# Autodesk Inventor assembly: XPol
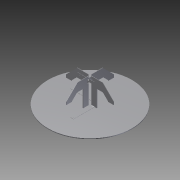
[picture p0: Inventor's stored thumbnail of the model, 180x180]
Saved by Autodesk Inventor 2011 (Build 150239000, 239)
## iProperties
Created: 2014-11
Part Number: XPol
Document SubType Name: Assembly
Designer: Evgeny
Author: Evgeny
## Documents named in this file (5)
- D:\Autodesk Invertor 2011\Projects2014\Antenna\Xpol\XPol.iam
- D:\Autodesk Invertor 2011\Projects2014\Antenna\Xpol\XPref.ipt
- D:\Autodesk Invertor 2011\Projects2014\Antenna\Xpol\Xp1.ipt
- D:\Autodesk Invertor 2011\Projects2014\Antenna\Xpol\XPstripeL.ipt
- D:\Autodesk Invertor 2011\Projects2014\Antenna\Xpol\XPstripe.ipt
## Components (7 placed, 4 different names)
1. XPref:1 — Совмещение:1, Совмещение:2, Совмещение:3, Совмещение:4, Совмещение:5, Совмещение:6, Совмещение:7, Совмещение:8, Совмещение:9, Совмещение:10, Совмещение:11, Совмещение:12, Совмещение:14, Совмещение:16
2. Xp1:1 — Совмещение:1, Совмещение:2, Совмещение:3, Совмещение:13
3. Xp1:2 — Совмещение:4, Совмещение:5, Совмещение:6, Совмещение:15
4. Xp1:3 — Совмещение:7, Совмещение:8, Совмещение:9, Заподлицо:2
5. Xp1:4 — Совмещение:10, Совмещение:11, Совмещение:12, Заподлицо:1
6. XPstripeL:1 — Совмещение:13, Совмещение:14, Заподлицо:1
7. XPstripe:1 — Совмещение:15, Совмещение:16, Заподлицо:2
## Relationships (18: Mate 16, Flush 2)
- Совмещение:1 [Mate]: XPref:1 ↔ Xp1:1
- Совмещение:2 [Mate]: XPref:1 ↔ Xp1:1
- Совмещение:3 [Mate]: XPref:1 ↔ Xp1:1
- Совмещение:4 [Mate]: XPref:1 ↔ Xp1:2
- Совмещение:5 [Mate]: XPref:1 ↔ Xp1:2
- Совмещение:6 [Mate]: XPref:1 ↔ Xp1:2
- Совмещение:7 [Mate]: XPref:1 ↔ Xp1:3
- Совмещение:8 [Mate]: XPref:1 ↔ Xp1:3
- Совмещение:9 [Mate]: XPref:1 ↔ Xp1:3
- Совмещение:10 [Mate]: XPref:1 ↔ Xp1:4
- Совмещение:11 [Mate]: XPref:1 ↔ Xp1:4
- Совмещение:12 [Mate]: XPref:1 ↔ Xp1:4
- Совмещение:13 [Mate]: Xp1:1 ↔ XPstripeL:1
- Совмещение:14 [Mate]: XPref:1 ↔ XPstripeL:1
- Заподлицо:1 [Flush]: Xp1:4 ↔ XPstripeL:1
- Совмещение:15 [Mate]: Xp1:2 ↔ XPstripe:1
- Совмещение:16 [Mate]: XPref:1 ↔ XPstripe:1
- Заподлицо:2 [Flush]: Xp1:3 ↔ XPstripe:1
